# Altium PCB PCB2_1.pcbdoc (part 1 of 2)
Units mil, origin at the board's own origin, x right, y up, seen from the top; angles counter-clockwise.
Board outline 4577.16 x 3522.49 mil, 4 copper layers (Top Layer, Inner1, Inner2, Bottom Layer); 102 components, 86 nets, 382 pads, 182 vias.
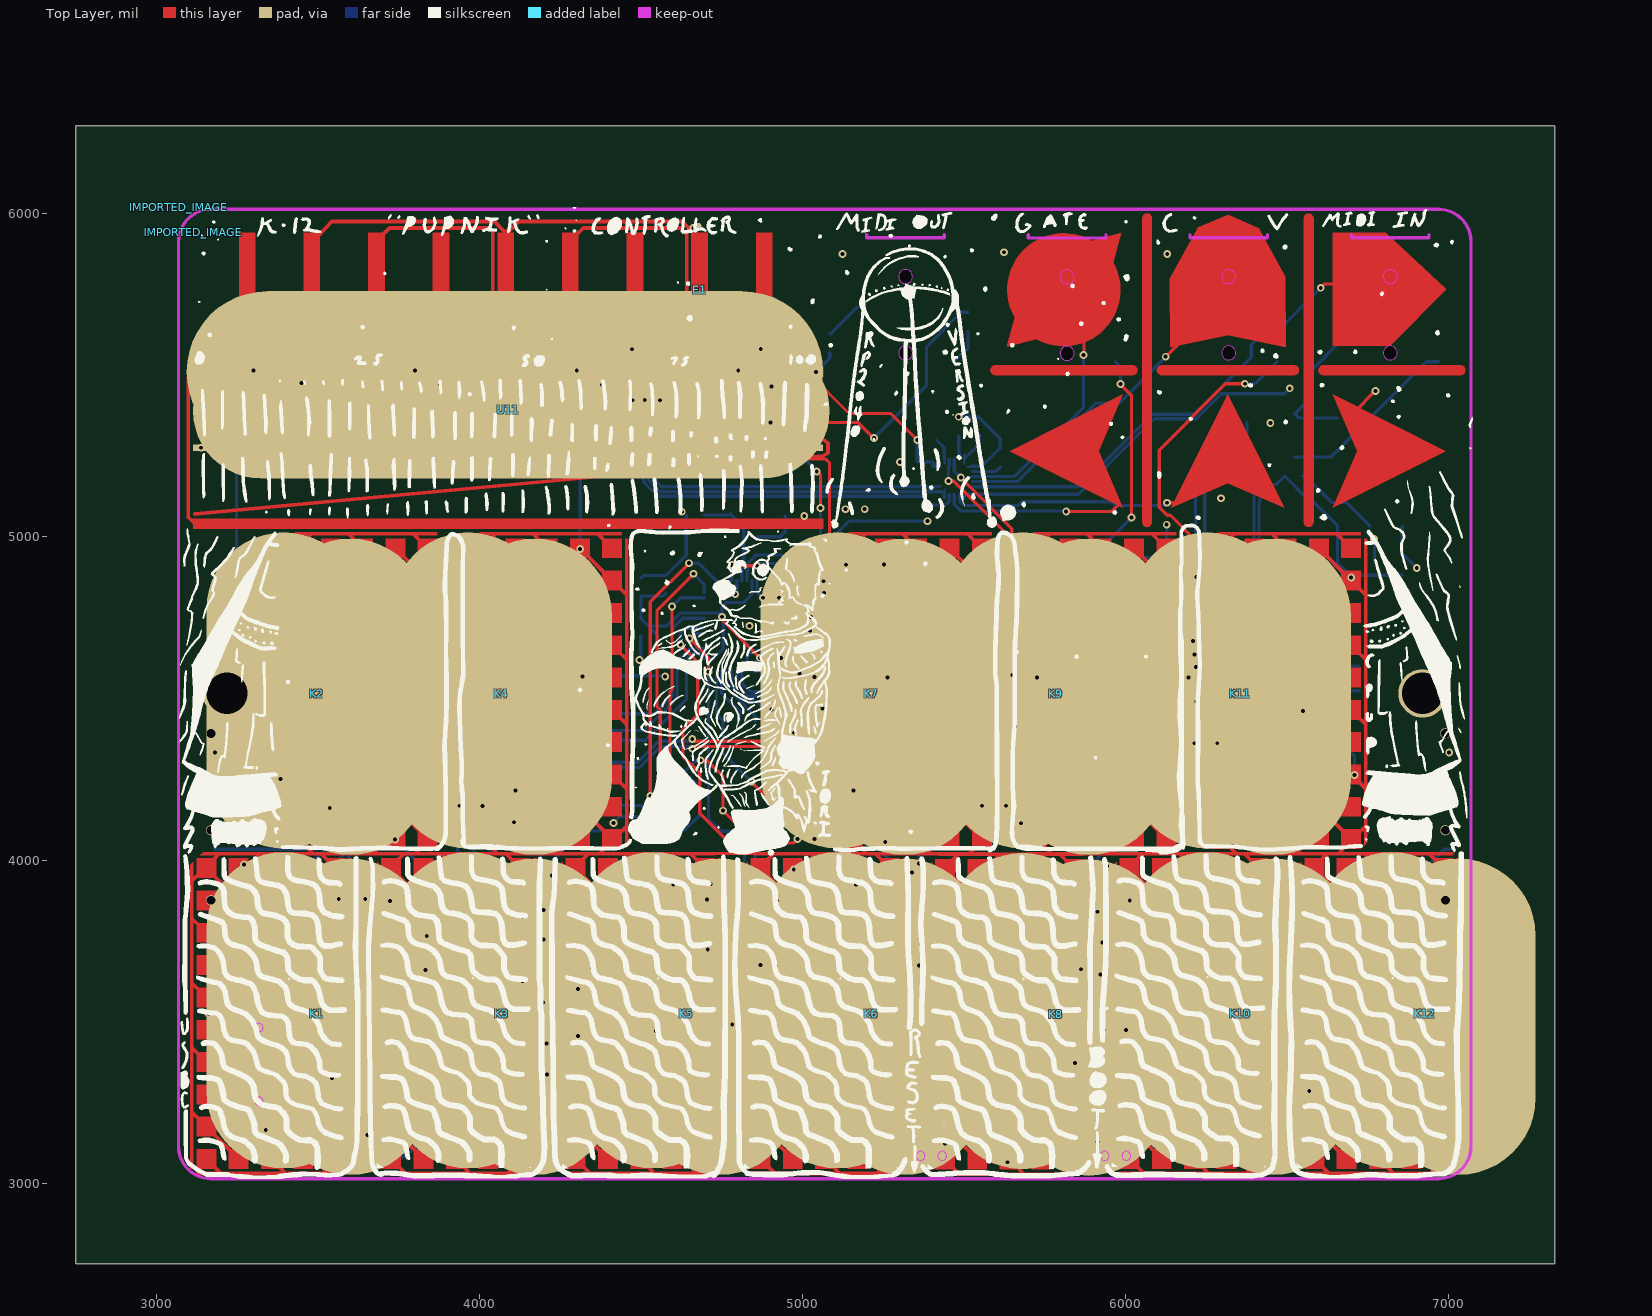
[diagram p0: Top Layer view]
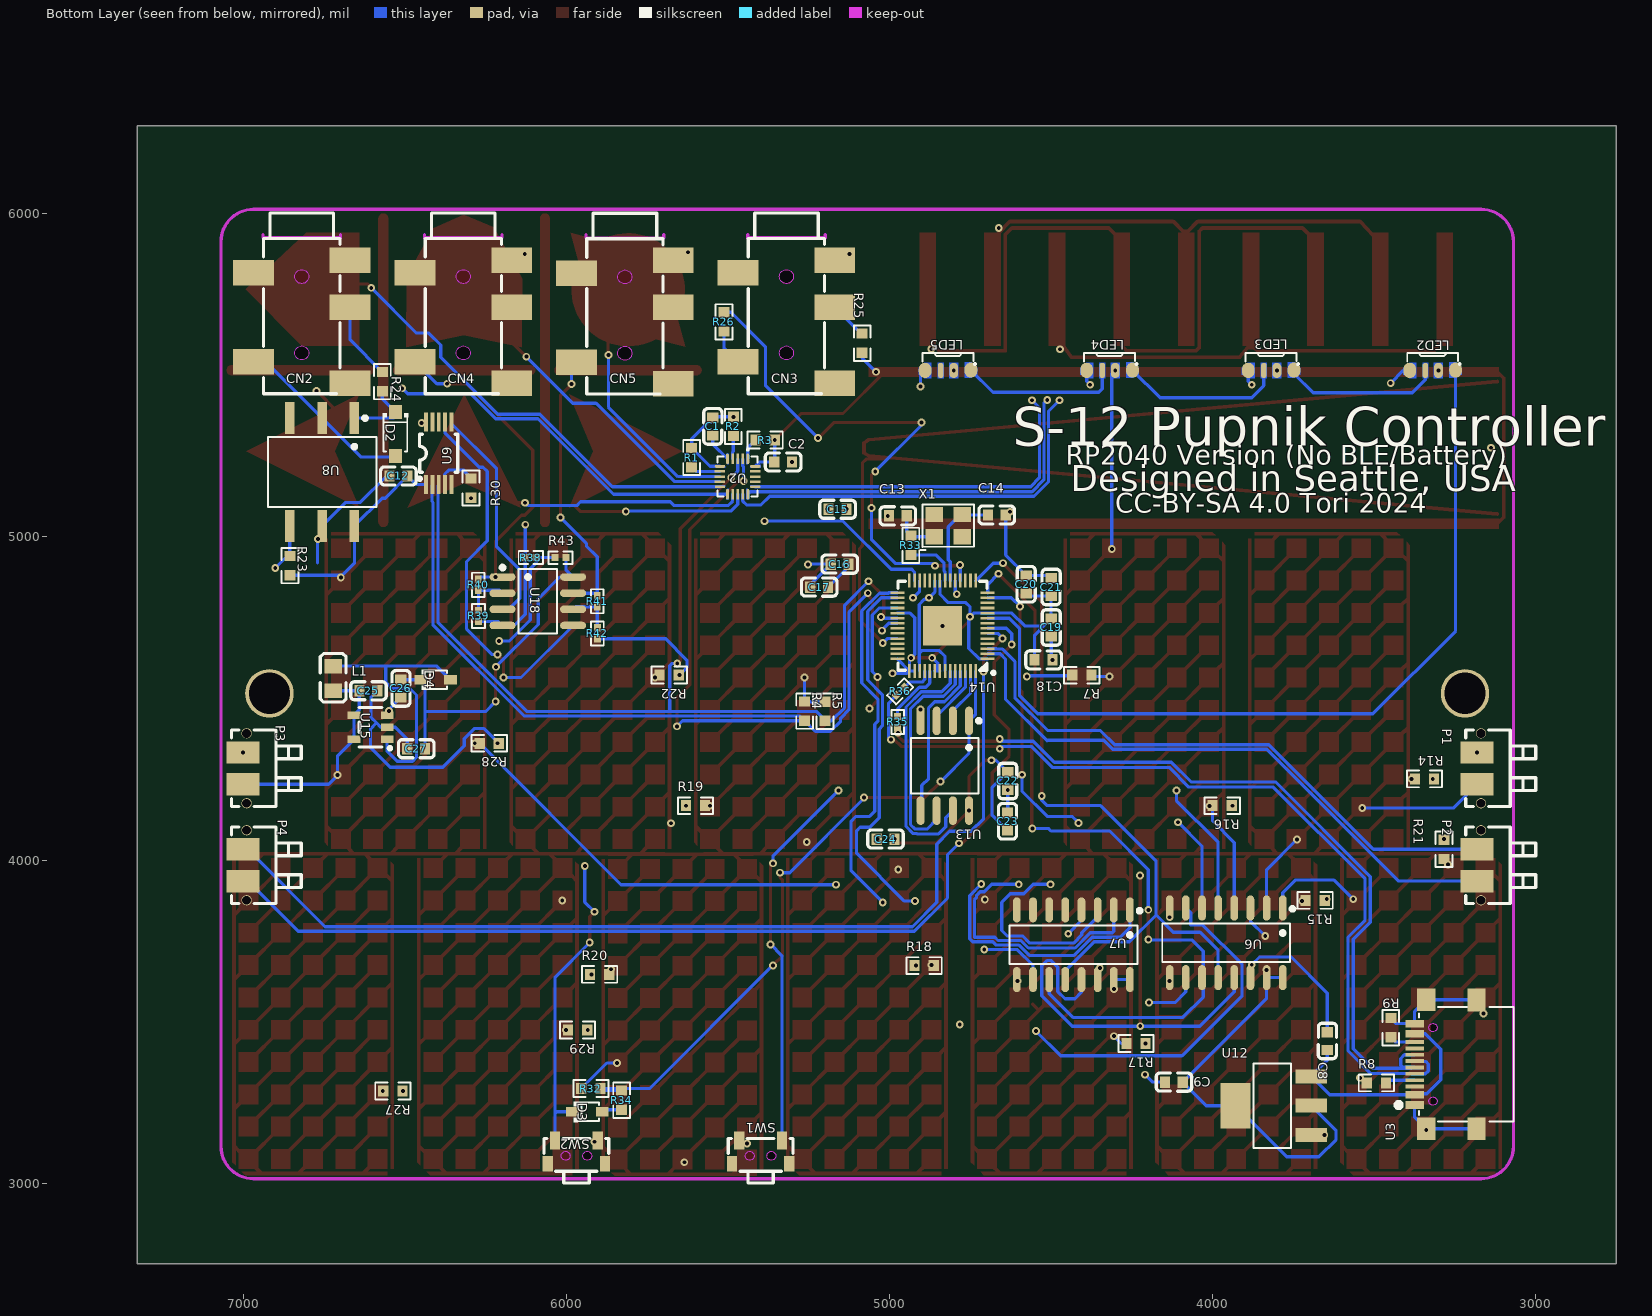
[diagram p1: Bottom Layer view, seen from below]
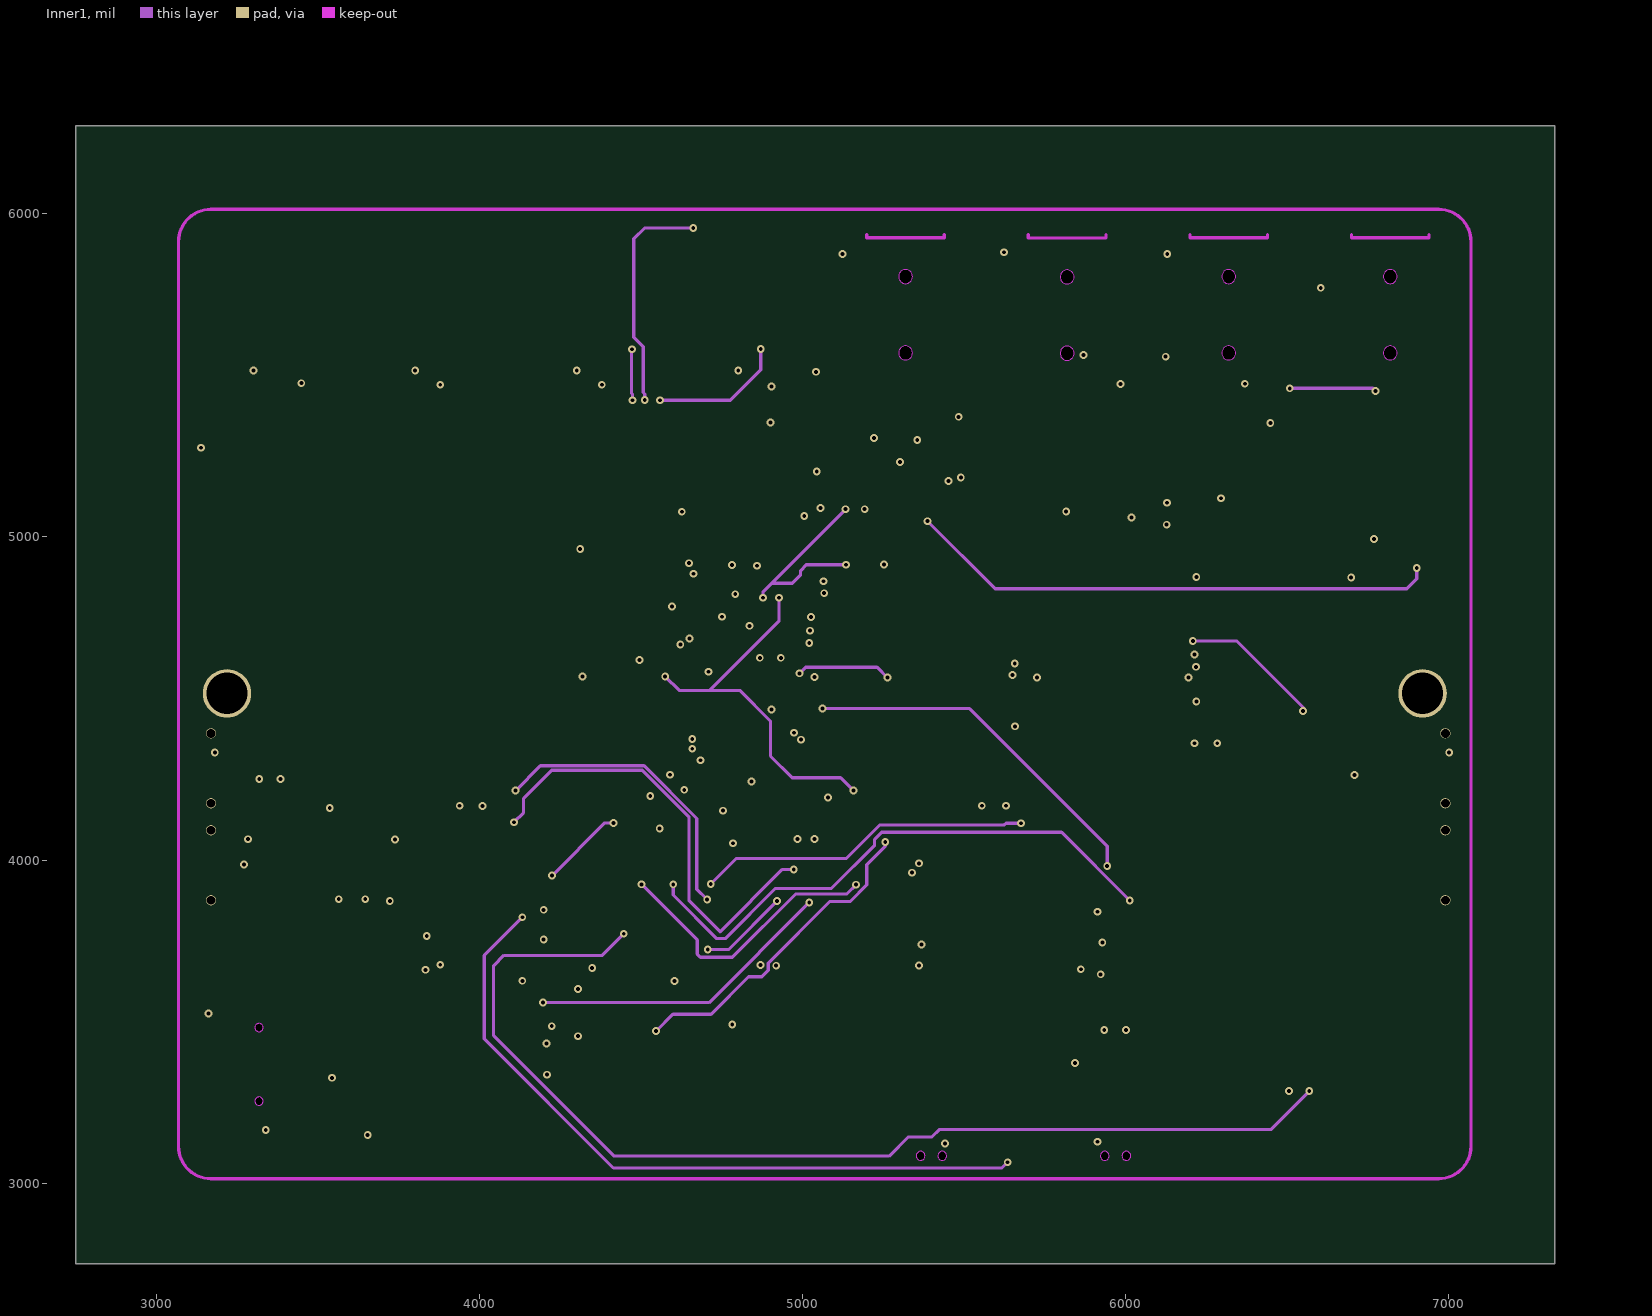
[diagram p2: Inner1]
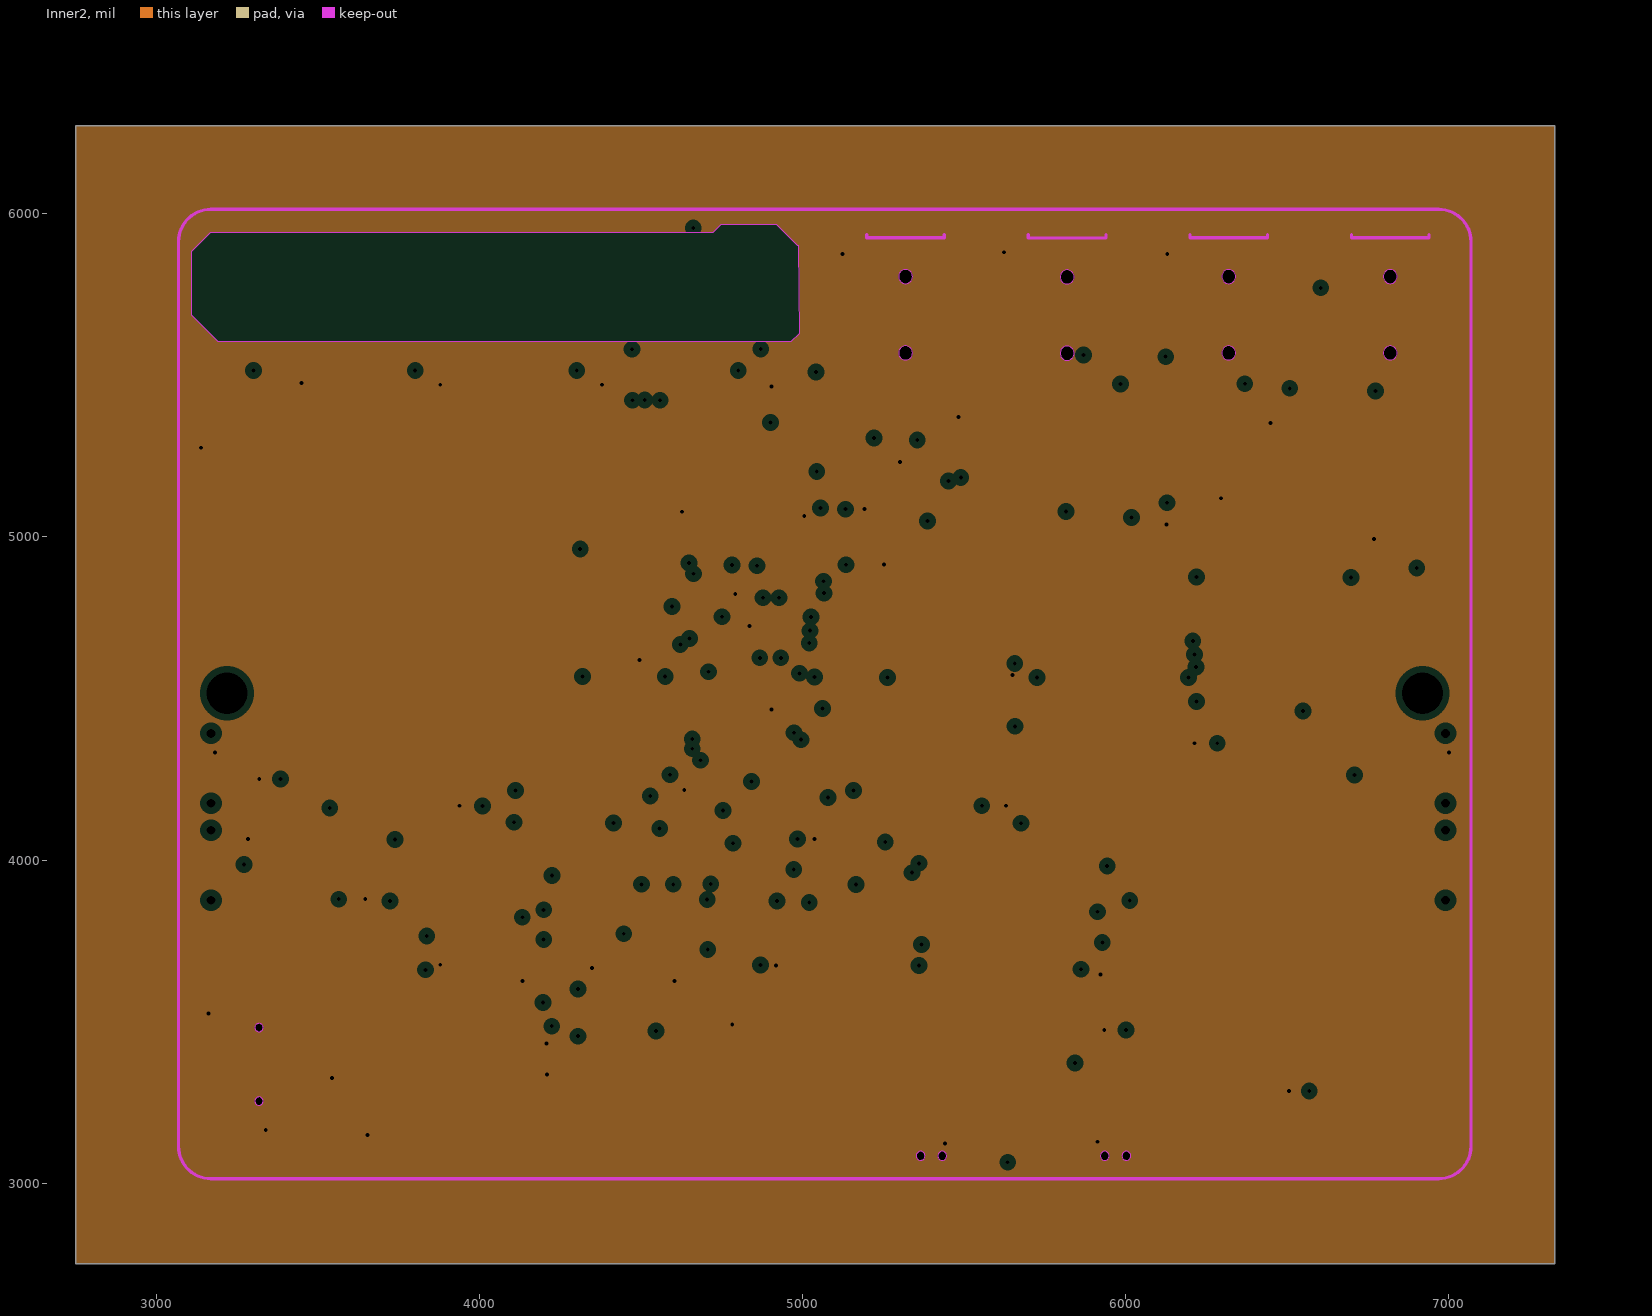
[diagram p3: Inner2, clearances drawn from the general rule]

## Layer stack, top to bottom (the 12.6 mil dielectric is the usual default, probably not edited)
Top Layer: signal copper (thickness not stored)
Dielectric: dielectric 12.6, FR-4, Dk 4.8
Inner1: signal copper (thickness not stored)
Dielectric: dielectric 12.6, FR-4, Dk 4.8
Inner2: plane copper (thickness not stored)
Dielectric: dielectric 12.6, FR-4, Dk 4.8
Bottom Layer: signal copper (thickness not stored)

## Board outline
7327.16,2750 2750,2750 2750,6272.49 7327.16,6272.49

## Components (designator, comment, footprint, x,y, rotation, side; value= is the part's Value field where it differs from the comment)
C1 "0.1u" C0603 5546.64,5341.97 r270 bottom
C2 "0.1u" C0603 5328.64,5231.97 r180 bottom
C8 "10u" C0603 3644.64,3439.85 r270 bottom
C9 "10u" C0603 4119.64,3312.97 r0 bottom
C12 "0.1u" C0603 6519.26,5188.72 r180 bottom
C13 "CAP_0603" C0603 4973.64,5064.97 r180 bottom
C14 "CAP_0603" C0603 4667.64,5067.97 r180 bottom
C15 "CAP_0603" C0603 5160.52,5085.97 r0 bottom
C16 "CAP_0603" C0603 5154.19,4916.04 r0 bottom
C17 "CAP_0603" C0603 5217.64,4844.97 r0 bottom
C18 "CAP_0603" C0603 4523.08,4619.53 r0 bottom
C19 "CAP_0603" C0603 4499.08,4720.09 r90 bottom
C20 "CAP_0603" C0603 4576.82,4853.09 r270 bottom
C21 "CAP_0603" C0603 4499.64,4844.97 r270 bottom
C22 "CAP_0603" C0603 4633.64,4244.97 r90 bottom
C23 "CAP_0603" C0603 4634.5,4119.65 r270 bottom
C24 "CAP_0603" C0603 5011.64,4064.97 r180 bottom
C25 "4.7u" C0603 6612.64,4523.97 r0 bottom
C26 "22p" C0603 6511.68,4531.07 r270 bottom
C27 "1u" C0603 6464.45,4344.69 r0 bottom
CN2 "MIDI IN" AUDIO-SMD_PJ-327A5JJ 6818.64,5665.97 r180 bottom
CN3 "MIDI OUT" AUDIO-SMD_PJ-327A5JJ 5318.64,5665.97 r180 bottom
CN4 "CV" AUDIO-SMD_PJ-327A5JJ 6318.64,5665.97 r180 bottom
CN5 "GT" AUDIO-SMD_PJ-327A5JJ 5818.64,5664.97 r180 bottom
D2 "1N4148W_C81598" SOD-123F_L2.7-W1.6-LS3.8-RD 6528.64,5318.97 r270 bottom
D3 "1N5819WS_C191023" SOD-323_L1.8-W1.3-LS2.5-RD 5934.64,3220.97 r180 bottom
D4 "1N5819WS_C191023" SOD-323_L1.8-W1.3-LS2.5-RD 6404.64,4557.97 r180 bottom
E1 "enc" enc 3236.85,5942.35 r0 top
IMPORTED_IMAGE "IMPORTED_IMAGE" IMPORTED_IMAGE 3070.08,6020.97 r0 top
IMPORTED_IMAGE "IMPORTED_IMAGE" IMPORTED_IMAGE 3113.64,5942.97 r0 top
K1 "key" key 3354.64,3524.97 r0 top
K2 "key" key 3639.64,4514.97 r180 top
K3 "key" key 3926.64,3524.97 r0 top
K4 "key" key 4210.64,4514.97 r180 top
K5 "key" key 4497.64,3524.97 r0 top
K6 "key" key 5069.64,3524.97 r0 top
K7 "key" key 5354.64,4514.97 r180 top
K8 "key" key 5640.64,3522.97 r0 top
K9 "key" key 5925.64,4514.97 r180 top
K10 "key" key 6211.64,3524.97 r0 top
K11 "key" key 6497.64,4514.97 r180 top
K12 "key" key 6783.64,3524.97 r0 top
L1 "CMI201209U2R2KT" L0805 6721.45,4562.39 r270 bottom
LED2 "SK6812SIDE-A-RVS" LED-SMD_4P-L4.0-W1.6-L 3318.64,5515.97 r0 bottom
LED3 "SK6812SIDE-A-RVS" LED-SMD_4P-L4.0-W1.6-L 3818.64,5515.97 r0 bottom
LED4 "SK6812SIDE-A-RVS" LED-SMD_4P-L4.0-W1.6-L 4318.64,5515.97 r0 bottom
LED5 "SK6812SIDE-A-RVS" LED-SMD_4P-L4.0-W1.6-L 4818.64,5515.97 r0 bottom
P1 "PogoPIN 2PIN 2.54mm" "POGOPIN 2PIN 2.5MM" 3078.64,4165.97 r270 bottom
P2 "PogoPIN 2PIN 2.54mm" "POGOPIN 2PIN 2.5MM" 3078.64,3865.97 r270 bottom
P3 "PogoPIN 2PIN 2.54mm" "POGOPIN 2PIN 2.5MM" 6898.64,4165.97 r270 bottom
P4 "PogoPIN 2PIN 2.54mm" "POGOPIN 2PIN 2.5MM" 6898.64,3865.97 r270 bottom
R1 "75k" R0603 5611.98,5245.63 r270 bottom
R2 "10k" R0603 5483.07,5342.12 r270 bottom
R3 "10k" R0603 5384.64,5299.97 r0 bottom
R4 "10k" R0603 5262.37,4460.89 r270 bottom
R5 "10k" R0603 5199.37,4460.6 r270 bottom
R7 "10k" R0603 4404.46,4572.11 r0 bottom
R8 "5.1k" R0603 3492.89,3310.64 r180 bottom
R9 "5.1k" R0603 3448.23,3481.26 r270 bottom
R14 "100K" R0603 3343.99,4251.29 r0 bottom
R15 "100K" R0603 3682.48,3875.29 r0 bottom
R16 "100K" R0603 3970.14,4168.29 r0 bottom
R17 "100K" R0603 4236.89,3432.29 r0 bottom
R18 "100K" R0603 4892.59,3673.29 r180 bottom
R19 "100K" R0603 5600.04,4168.29 r180 bottom
R20 "100K" R0603 5896.79,3646.29 r180 bottom
R21 "100K" R0603 3283.3,4033.31 r270 bottom
R22 "100K" R0603 5681.49,4572.46 r0 bottom
R23 "470" R0603 6855.3,4911.31 r270 bottom
R24 "220" R0603 6569.19,5480.67 r270 bottom
R25 "33" R0603 5084.16,5599.63 r270 bottom
R26 "10" R0603 5512.16,5665.59 r90 bottom
R27 "100K" R0603 6536.64,3284.97 r0 bottom
R28 "100K" R0603 6238.48,4361.46 r0 bottom
R29 "100K" R0603 5964.99,3474.46 r0 bottom
R30 "5.1k" R0603 6294.97,5151.26 r90 bottom
R32 "Res_0603" R0603 5923.64,3292.97 r180 bottom
R33 "Res_0603" R0603 4933.64,4973.97 r270 bottom
R34 "Res_0603" R0603 5828.64,3256.97 r270 bottom
R35 "Res_0402" R0402 4974.53,4427.42 r270 bottom
R36 "Res_0402" R0402 4966.64,4521.97 r315 bottom
R38 "Res_0402" R0402 6109.83,4936.4 r180 bottom
R39 "Res_0402" R0402 6271.52,4755.41 r90 bottom
R40 "Res_0402" R0402 6272.24,4852 r90 bottom
R41 "Res_0402" R0402 5904.24,4801 r270 bottom
R42 "Res_0402" R0402 5903.6,4701.72 r90 bottom
R43 "Res_0402" R0402 6018.24,4936 r180 bottom
SW1 "RST" SW-SMD_L4.7-W3.5-P3.35-EH 5398.64,3095.97 r0 bottom
SW2 "BOOT" SW-SMD_L4.7-W3.5-P3.35-EH 5968.64,3095.97 r0 bottom
U2 "MPR121QR2" QFN-20_L3.0-W3.0-P0.40-BL 5469.64,5186.97 r0 bottom
U3 "GT-USB-9047A" USB-C-SMD_GT-USB-9047A 3278.64,3367.97 r90 bottom
U6 "MCP3008-I/SL" SOIC-16_L9.9-W3.9-P1.27-LS6.0-BL 3957.64,3743.97 r0 bottom
U7 "MCP3008-I/SL" SOIC-16_L9.9-W3.9-P1.27-LS6.0-BL 4430.64,3737.97 r0 bottom
U8 "H11L1VSMT&amp;R" SMD-6_L8.6-W6.4-P2.54-LS9.4-BL 6755.64,5200.97 r0 bottom
U9 "MCP4728-E/UN" MSOP-10_L3.0-W3.0-P0.50-LS5.0-TL 6394.64,5258.97 r90 bottom
U11 "farts" farts 3093.64,5525.97 r0 top
U12 "AMS1117-3.3_C6186" SOT-223-3_L6.5-W3.4-P2.30-LS7.0-BR 3811.64,3239.97 r180 bottom
U13 "W25Q128JVSIQ" SOIC-8_L5.3-W5.3-P1.27-LS8.0-BL 4828.64,4291.97 r0 bottom
U14 "RP2040_C2040" LQFN-56_L7.0-W7.0-P0.4-EP 4835.64,4724.98 r0 bottom
U15 "TPS61041DBVR" SOT-23-5_L3.0-W1.7-P0.95-LS2.8-BR 6605.64,4410.97 r180 bottom
U18 "MCP6002T-I/SN" SOIC-8_L4.9-W3.9-P1.27-LS6.0-BL 6088.24,4801 r270 bottom
X1 "X322512MSB4SI" OSC-SMD_4P-L3.2-W2.5-BL 4817.64,5034.97 r180 bottom

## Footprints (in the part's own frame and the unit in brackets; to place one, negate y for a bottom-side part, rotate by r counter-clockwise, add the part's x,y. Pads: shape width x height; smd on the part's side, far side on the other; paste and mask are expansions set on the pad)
AUDIO-SMD_PJ-327A5JJ [mm]
  rect 3.2x2 smd: 1(3.8,4.85) 2(-3.8,3.85) 3(3.8,1.15) 4(-3.8,-3.15) 5(3.8,-4.85)
  Board Outline Layer lines w0.254: 3.048,6.604 -3.048,6.604 ; 3.048,6.604 -3.048,6.604 ; 3.048,6.604 3.048,6.858 3.048,6.604 ; -3.048,6.604 -3.048,6.858 -3.048,6.604
  Multi-Layer board cut-out: -0.55,3.55 -0.496,3.789 -0.343,3.98 -0.123,4.086 0.122,4.086 0.343,3.98 0.495,3.789 0.55,3.55 0.55,3.55 0.495,3.311 0.343,3.12 0.122,3.014 -0.123,3.014 -0.343,3.12 -0.496,3.311 -0.55,3.55
  Multi-Layer board cut-out: -0.55,-2.45 -0.496,-2.211 -0.343,-2.02 -0.123,-1.914 0.122,-1.914 0.343,-2.02 0.495,-2.211 0.55,-2.45 0.55,-2.45 0.495,-2.689 0.343,-2.88 0.122,-2.986 -0.123,-2.986 -0.343,-2.88 -0.496,-2.689 -0.55,-2.45
  Multi-Layer keep-out region: -0.55,3.55 -0.496,3.789 -0.343,3.98 -0.123,4.086 0.122,4.086 0.343,3.98 0.495,3.789 0.55,3.55 0.55,3.55 0.495,3.311 0.343,3.12 0.122,3.014 -0.123,3.014 -0.343,3.12 -0.496,3.311 -0.55,3.55
  Multi-Layer keep-out region: -0.55,-2.45 -0.496,-2.211 -0.343,-2.02 -0.123,-1.914 0.122,-1.914 0.343,-2.02 0.495,-2.211 0.55,-2.45 0.55,-2.45 0.495,-2.689 0.343,-2.88 0.122,-2.986 -0.123,-2.986 -0.343,-2.88 -0.496,-2.689 -0.55,-2.45
  silkscreen extent -3,-5.65 3,8.55
C0603 [mm]
  rect 0.8x0.9 smd: 1(-0.7,0) 2(0.7,0)
  silkscreen extent -1.41,-0.71 1.39,0.72
enc [mil]
  round 20 smd: 1(1645,-370) 2(1440,20) 3(1245,-375)
farts [mil]
  oval 1970x500 smd: 1(985,-15)
  oval 1970x420 smd: 2(1005,-135.69)
  rect 1950x20 smd: 3(995,-250)
  Top Layer region: 1970,-470 1970,-500 20,-500 20,-487.07 1.46,-468.54 1.46,-468.54 0.38,-466.91 0,-465 0,-465 0,-35 0.38,-33.09 1.46,-31.46 1.46,-31.46 1.46,-31.46 20,-12.93 20,0 1970,0 1970,-30 20,-30 20,-27.07 10,-37.07 10,-462.93 20,-472.93 20,-470
  Top Layer region: 25.46,-459.98 25.23,-459.99 25,-460 25,-460 23.09,-459.62 21.46,-458.54 20.38,-456.91 20,-455 20,-455 20.6,-452.63 22.24,-450.83 24.54,-450.02 24.54,-450.02 1968.42,-270.13 1980,-263.25 1980,-237.68 1968.28,-229.86 24.54,-49.98 24.54,-49.98 22.24,-49.17 20.6,-47.37 20,-45 20,-45 20.38,-43.09 21.46,-41.46 23.09,-40.38 25,-40 25,-40 25.23,-40.01 25.46,-40.02 25.46,-40.02 1970.46,-220.02 1970.46,-220.02 1971.67,-220.29 1972.77,-220.84 1972.77,-220.84 1972.77,-220.84 1987.77,-230.84 1987.77,-230.84 1989.41,-232.64 1990,-235 1990,-235 1990,-266.1 1989.34,-268.57 1987.55,-270.4 1987.55,-270.4 1987.55,-270.4 1972.55,-279.3 1971.54,-279.76 1970.46,-279.98 1970.46,-279.98 1970.46,-279.98
IMPORTED_IMAGE [mil]
  silkscreen extent 0,-3007 4004,0
key [mil]
  oval 480x980 smd: 1(40,10) 2(245,-10)
  Top Layer region: 191 vertices and 0 holes, not listed, extent -250,-480 230,500
  Top Layer region: 189 vertices and 0 holes, not listed, extent -230,-500 250,480
L0805 [mil]
  rect 44.59x54.21 smd: 1(-38.04,0) 2(38.04,0)
  silkscreen extent -77,-40 73,40
LED-SMD_4P-L4.0-W1.6-L [mm]
  oval 1x1.2 smd: 1(-1.8,-0.012) 4(1.8,0.013)
  oval 0.7x1.2 smd: 2(-0.45,0.013)
  oval 0.45x1.2 smd: 3(0.575,0.013)
  Top Layer region: 1.3,0.612 1.3,-0.588 1.85,-0.587 1.85,-0.188 2.3,-0.188 2.3,0.362 1.85,0.362 1.85,0.612
  Top Layer region: 0.35,-0.588 0.8,-0.588 0.8,0.612 0.35,0.612
  Top Layer region: -0.8,0.613 -0.8,-0.587 -0.1,-0.587 -0.1,0.613
  Top Layer region: -1.3,0.588 -1.3,-0.612 -1.85,-0.612 -1.85,-0.212 -2.3,-0.212 -2.3,0.338 -1.85,0.338 -1.85,0.588
  silkscreen extent -2.2,-1.36 2,-0.41
LQFN-56_L7.0-W7.0-P0.4-EP [mm]
  rect 1.1x0.2 smd: 1(-3.55,2.6) 2(-3.55,2.2) 3(-3.55,1.8) 4(-3.55,1.4) 5(-3.55,1) 6(-3.55,0.6) 7(-3.55,0.2) 8(-3.55,-0.2) 9(-3.55,-0.6) 10(-3.55,-1) 11(-3.55,-1.4) 12(-3.55,-1.8) 13(-3.55,-2.2) 14(-3.55,-2.6) 29(3.55,-2.6) 30(3.55,-2.2) 31(3.55,-1.8) 32(3.55,-1.4) 33(3.55,-1) 34(3.55,-0.6) 35(3.55,-0.2) 36(3.55,0.2) 37(3.55,0.6) 38(3.55,1) 39(3.55,1.4) 40(3.55,1.8) 41(3.55,2.2) 42(3.55,2.6)
  rect 0.2x1.1 smd: 15(-2.6,-3.55) 16(-2.2,-3.55) 17(-1.8,-3.55) 18(-1.4,-3.55) 19(-1,-3.55) 20(-0.6,-3.55) 21(-0.2,-3.55) 22(0.2,-3.55) 23(0.6,-3.55) 24(1,-3.55) 25(1.4,-3.55) 26(1.8,-3.55) 27(2.2,-3.55) 28(2.6,-3.55) 43(2.6,3.55) 44(2.2,3.55) 45(1.8,3.55) 46(1.4,3.55) 47(1,3.55) 48(0.6,3.55) 49(0.2,3.55) 50(-0.2,3.55) 51(-0.6,3.55) 52(-1,3.55) 53(-1.4,3.55) 54(-1.8,3.55) 55(-2.2,3.55) 56(-2.6,3.55)
  rect 3.1x3.1 smd: 57(0,0)
  silkscreen extent -4.13,-3.5 3.5,3.83
MSOP-10_L3.0-W3.0-P0.50-LS5.0-TL [mil]
  rect 59.05x12 smd: 1(-96.5,39.37) 2(-96.5,19.68) 3(-96.5,0) 4(-96.5,-19.69) 5(-96.5,-39.37) 6(96.5,-39.37) 7(96.5,-19.69) 8(96.5,0) 9(96.5,19.68) 10(96.5,39.37)
  silkscreen extent -84,-59 59,64
OSC-SMD_4P-L3.2-W2.5-BL [mm]
  rect 1.4x1.2 smd: 1(-1.1,-0.875) 2(1.1,-0.875) 3(1.1,0.875) 4(-1.1,0.875)
  silkscreen extent -2.29,-1.9 2.03,1.65
"POGOPIN 2PIN 2.5MM" [mm]
  rect 1.75x2.6 smd: 1(-4.25,-2.6) 2(-1.75,-2.6)
  round 0.8 hole 0.7: 3(-5.75,-2.3) 4(-0.25,-2.3)
  silkscreen extent -6,-3.5 0,2
QFN-20_L3.0-W3.0-P0.40-BL [mm]
  oval 0.224x0.825 smd: 1(-0.8,-1.388) 5(0.8,-1.388) 11(0.8,1.388) 15(-0.8,1.388)
  rect 0.2x0.825 smd: 2(-0.4,-1.388) 3(0,-1.388) 4(0.4,-1.388) 12(0.4,1.388) 13(0,1.388) 14(-0.4,1.388)
  oval 0.825x0.224 smd: 6(1.388,-0.8) 10(1.388,0.8) 16(-1.387,0.8) 20(-1.388,-0.8)
  rect 0.825x0.2 smd: 7(1.388,-0.4) 8(1.388,0) 9(1.388,0.4) 17(-1.387,0.4) 18(-1.387,0) 19(-1.387,-0.4)
  Top Layer region: 0.688,-1.8 0.688,-0.975 0.8,-0.975 0.912,-1.388 0.912,-1.8
  Top Layer region: -1.8,-0.688 -0.975,-0.688 -0.975,-0.8 -1.388,-0.912 -1.8,-0.912
  Top Layer region: -0.688,1.8 -0.688,0.975 -0.8,0.975 -0.912,1.388 -0.912,1.8
  Top Layer region: 1.8,0.688 0.975,0.688 0.975,0.8 1.388,0.912 1.8,0.912
  Top Layer region: 1.8,-0.688 0.975,-0.688 0.975,-0.8 1.388,-0.912 1.8,-0.912
  Top Layer region: 0.688,1.8 0.688,0.975 0.8,0.975 0.912,1.388 0.912,1.8
  Top Layer region: -1.8,0.688 -0.975,0.688 -0.975,0.8 -1.387,0.912 -1.8,0.912
  Top Layer region: -0.688,-1.8 -0.688,-0.975 -0.8,-0.975 -0.912,-1.388 -0.912,-1.8
  silkscreen extent -1.58,-2.17 1.58,1.58
R0402 [mm]
  rect 0.566x0.54 smd: 1(-0.433,0) 2(0.433,0)
  silkscreen extent -0.94,-0.5 0.94,0.5
R0603 [mil]
  rect 31.75x34.02 smd: 1(-29.66,0) 2(29.66,0)
  silkscreen extent -55,-26 55,26
SMD-6_L8.6-W6.4-P2.54-LS9.4-BL [mil]
  rect 29.76x99.37 smd: 1(-100,-166.81) 2(0,-166.81) 3(100,-166.81) 4(100,166.81) 5(0,166.81) 6(-100,166.81)
  silkscreen extent -168,-173 168,108
SOD-123F_L2.7-W1.6-LS3.8-RD [mm]
  rect 1.1x1 smd: 1(-1.735,0) 2(1.735,0)
  silkscreen extent -1.6,-1 1.38,1
SOD-323_L1.8-W1.3-LS2.5-RD [mm]
  rect 1x0.75 smd: 1(-1.173,0) 2(1.173,0)
  silkscreen extent -1.08,-0.8 0.9,0.8
SOIC-8_L4.9-W3.9-P1.27-LS6.0-BL [mm]
  oval 0.588x2.045 smd: 1(-1.905,-2.772) 2(-0.635,-2.772) 3(0.635,-2.772) 4(1.905,-2.772) 5(1.905,2.772) 6(0.635,2.772) 7(-0.635,2.772) 8(-1.905,2.772)
  silkscreen extent -2.8,-2.92 2.53,1.52
SOIC-8_L5.3-W5.3-P1.27-LS8.0-BL [mm]
  oval 0.63x2.25 smd: 1(-1.905,-3.53) 2(-0.635,-3.53) 3(0.635,-3.53) 4(1.905,-3.53) 5(1.905,3.53) 6(0.635,3.53) 7(-0.635,3.53) 8(-1.905,3.53)
  silkscreen extent -2.82,-3.68 2.64,2.18
SOIC-16_L9.9-W3.9-P1.27-LS6.0-BL [mil]
  oval 23.7x77.6 smd: 1(-175,-107.7) 2(-125,-107.7) 3(-75,-107.7) 4(-25,-107.7) 5(25,-107.7) 6(75,-107.7) 7(125,-107.7) 8(175,-107.7) 9(175,107.7) 10(125,107.7) 11(75,107.7) 12(25,107.7) 13(-25,107.7) 14(-75,107.7) 15(-125,107.7) 16(-175,107.7)
  silkscreen extent -211,-111 198,60
SOT-23-5_L3.0-W1.7-P0.95-LS2.8-BR [mm]
  rect 1x0.6 smd: 1(1.3,-0.95) 2(1.3,0) 3(1.3,0.95) 4(-1.3,0.95) 5(-1.3,-0.95)
  silkscreen extent -0.9,-1.78 1.65,1.55
SOT-223-3_L6.5-W3.4-P2.30-LS7.0-BR [mm]
  rect 2.5x1.1 smd: 1(2.97,-2.3) 2(2.97,0) 3(2.97,2.3)
  rect 2.34x3.6 smd: 4(-2.97,0)
  silkscreen extent -1.57,-3.33 1.37,3.33
SW-SMD_L4.7-W3.5-P3.35-EH [mm]
  rect 0.8x1.4 smd: 1(-1.675,-0.917) 2(1.675,-0.917)
  rect 0.8x1.2 smd: 3(-2.25,0.917) 4(2.25,0.917)
  Multi-Layer board cut-out: -0.5,0.282 -0.535,0.131 -0.632,0.009 -0.772,-0.059 -0.928,-0.059 -1.068,0.009 -1.165,0.131 -1.2,0.282 -1.2,0.282 -1.165,0.434 -1.068,0.556 -0.928,0.624 -0.772,0.624 -0.632,0.556 -0.535,0.434 -0.5,0.282
  Multi-Layer board cut-out: 1.2,0.282 1.165,0.131 1.068,0.009 0.928,-0.059 0.772,-0.059 0.632,0.009 0.535,0.131 0.5,0.282 0.5,0.282 0.535,0.434 0.632,0.556 0.772,0.624 0.928,0.624 1.068,0.556 1.165,0.434 1.2,0.282
  Multi-Layer keep-out region: -0.5,0.282 -0.535,0.131 -0.632,0.009 -0.772,-0.059 -0.928,-0.059 -1.068,0.009 -1.165,0.131 -1.2,0.282 -1.2,0.282 -1.165,0.434 -1.068,0.556 -0.928,0.624 -0.772,0.624 -0.632,0.556 -0.535,0.434 -0.5,0.282
  Multi-Layer keep-out region: 1.2,0.282 1.165,0.131 1.068,0.009 0.928,-0.059 0.772,-0.059 0.632,0.009 0.535,0.131 0.5,0.282 0.5,0.282 0.535,0.434 0.632,0.556 0.772,0.624 0.928,0.624 1.068,0.556 1.165,0.434 1.2,0.282
  silkscreen extent -2.54,-1.07 2.54,2.43
USB-C-SMD_GT-USB-9047A [mm]
  rect 1.8x1.45 smd: 12(-5.07,1.524) 13(5.07,1.524)
  rect 1.8x1.4 smd: 14(-5.07,-2.436) 15(5.07,-2.436)
  rect 0.6x1.45 smd: A1B12(-3.2,2.437) A4B9(-2.4,2.437) A9B4(2.4,2.437) A12B1(3.2,2.437)
  rect 0.3x1.45 smd: A5(-1.25,2.437) A6(-0.25,2.437) A7(0.25,2.437) A8(1.25,2.437) B5(1.75,2.437) B6(0.75,2.437) B7(-0.75,2.437) B8(-1.75,2.437)
  Multi-Layer board cut-out: 2.89,1.319 3.031,1.286 3.144,1.196 3.207,1.066 3.207,0.921 3.144,0.791 3.031,0.701 2.89,0.669 2.89,0.669 2.749,0.701 2.636,0.791 2.573,0.921 2.573,1.066 2.636,1.196 2.749,1.286 2.89,1.319
  Multi-Layer board cut-out: -2.89,1.318 -2.749,1.286 -2.636,1.196 -2.573,1.065 -2.573,0.921 -2.636,0.791 -2.749,0.7 -2.89,0.668 -2.89,0.668 -3.031,0.7 -3.144,0.791 -3.207,0.921 -3.207,1.065 -3.144,1.196 -3.031,1.286 -2.89,1.318
  Multi-Layer keep-out region: 2.89,1.319 3.031,1.286 3.144,1.196 3.207,1.066 3.207,0.921 3.144,0.791 3.031,0.701 2.89,0.669 2.89,0.669 2.749,0.701 2.636,0.791 2.573,0.921 2.573,1.066 2.636,1.196 2.749,1.286 2.89,1.319
  Multi-Layer keep-out region: -2.89,1.318 -2.749,1.286 -2.636,1.196 -2.573,1.065 -2.573,0.921 -2.636,0.791 -2.749,0.7 -2.89,0.668 -2.89,0.668 -3.031,0.7 -3.144,0.791 -3.207,0.921 -3.207,1.065 -3.144,1.196 -3.031,1.286 -2.89,1.318
  silkscreen extent -4.5,-5.36 4.5,3.89

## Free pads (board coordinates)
  round 150 hole 128: 73(3218.64,4515.97) 73(6918.64,4515.97)

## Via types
v1: diameter 24.02, hole 12.01, Top Layer to Bottom Layer, 182 vias

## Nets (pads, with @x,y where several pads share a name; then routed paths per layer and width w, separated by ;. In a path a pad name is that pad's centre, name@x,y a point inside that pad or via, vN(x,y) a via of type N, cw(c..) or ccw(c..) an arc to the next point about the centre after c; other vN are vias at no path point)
1V2: C15.1 C16.1 C17.1 U14.23 U14.45 U14.50 | length 1209.6
  Inner1 w10: v1(4877.64,4811.97) 4877.64,4830.65 4903.96,4856.97 ; v1(5132.96,5085.97) 4903.96,4856.97 ; v1(5134.64,4913.97) 5011.64,4913.97 4993.64,4895.97 4993.64,4882.97 4967.64,4856.97 4903.96,4856.97
  Bottom Layer w10: U14.50@4827.76,4585.21 4827.76,4630.09 4846.64,4648.97 4898.64,4648.97 4906.5,4641.11 4906.5,4611.11 ; U14.23@4859.26,4864.74 4859.26,4829.35 4881.64,4806.97 4891.64,4806.97 4907.64,4790.97 4907.64,4612.25 4906.5,4611.11 ; U14.45@4906.5,4585.21 4906.5,4611.11 ; C16.1@5126.64,4916.04 5126.64,4908.41 C17.1@5190.08,4844.97
3V3: C2.1 C9.1 C12.2 C18.2 C19.2 C20.2 C21.2 C22.2 C23.2 C24.2 C25.2 K1.1 K2.1 K3.1 K4.1 K5.1 K6.1 K7.1 K8.1 K9.1 K10.1 K11.1 K12.1 L1.2 LED2.2 LED3.2 LED4.2 LED5.2 P1.2 P3.2 R3.1 R4.1 R5.1 R7.1 R23.2 R25.2 R32.1 U2.20 U6.15 U6.16 U7.15 U7.16 U8.6 U9.1 U11.1 U12.2 U12.4 U13.8 U14.1 U14.10 U14.22 U14.33 U14.42 U14.43 U14.44 U14.48 U14.49 U15.4 U15.5 | length 8224.7
  Top Layer w10: U11.1@4078.64,5510.97 5014.64,5510.97 5143.64,5381.97 5272.98,5381.97 v1(5354.98,5299.97) ; K5.1@4537.64,3534.97 K5.1@4556.66,3553.98 ; v1(4683.64,4308.97) 4703.64,4308.97 4753.64,4258.97 v1(4753.64,4152.99) 4853.64,4052.99 ; 4728.64,4019.97 4853.64,4019.97 ; v1(4750.64,4752.97) 4750.64,4742.97 v1(4867.64,4625.97) v1(4932.64,4625.97) ; 4855.64,4021.97 4853.64,4019.97 ; v1(4984.08,4064.97) 4972.1,4052.99 4853.64,4052.99 ; 4853.64,4019.97 4853.64,4052.99
  Inner1 w10: v1(4990.64,4577.97) 5009.64,4596.97 5230.5,4596.97 v1(5262.37,4565.1)
  Bottom Layer w10: P1.2@3181,4234.87 3254.9,4160.97 v1(3536.64,4160.97) ; U12.2@3694.71,3239.97 3617.64,3162.89 3617.64,3134.97 3670.64,3081.97 3770.57,3081.97 U12.4@3928.57,3239.97 4019.08,3239.97 C9.1@4092.08,3312.97 3832.64,3572.41 U6.15@3832.64,3636.27 U6.16@3782.64,3636.27 ; U7.16@4255.64,3630.27 U7.15@4305.64,3630.27 ; v1(4300.93,5515.47) 4311.64,5504.76 v1(4311.64,4962.97) ; v1(4318.64,4567.97) 4370.66,4567.97 R7.1@4374.8,4572.11 ; C18.2@4550.64,4619.53 4550.64,4696.09 4521.97,4724.76 ; C20.2@4576.82,4825.53 4568.7,4817.41 C21.2@4499.64,4817.41 4499.64,4748.21 C19.2@4499.08,4747.65 4521.97,4724.76 ; C23.2@4634.5,4092.09 4682.64,4140.23 4682.64,4223.53 C22.2@4633.64,4272.53 4670.08,4308.97 v1(4683.64,4308.97) ; U14.1@4695.87,4622.61 4722.52,4622.61 4754.64,4654.73 4754.64,4748.97 v1(4750.64,4752.97) ; U14.22@4843.51,4864.74 4843.51,4822.84 4817.67,4797 4763.67,4797 4750.64,4783.97 v1(4750.64,4752.97) ; U14.48@4860.09,4586.04 U14.48@4859.26,4585.21 U14.49@4843.51,4585.21 4850.63,4592.33 4850.63,4608.96 v1(4867.64,4625.97) ; U14.44@4922.25,4585.21 U14.43@4938,4585.21 ; U14.42@4975.41,4622.61 U14.43@4938,4585.21 ; U14.33@4975.41,4764.34 4936.02,4764.34 4921.66,4749.98 4921.66,4636.95 v1(4932.64,4625.97) 4938.01,4620.6 U14.43@4938,4585.21 ; v1(4990.64,4577.97) 4945.25,4577.97 U14.43@4938,4585.21 ; v1(5041.64,5510.97) 5084.16,5553.49 R25.2@5084.16,5569.97 ; R5.1@5199.37,4490.26 5262.07,4490.26 R4.1@5262.37,4490.55 v1(5262.37,4565.1) ; v1(5354.98,5299.97) 5354.98,5233.19 C2.1@5356.2,5231.97 5401.51,5231.97 U2.20@5415.01,5218.47 ; v1(5842.64,3371.97) 5874.3,3371.97 R32.1@5953.3,3292.97 ; U9.1@6434.01,5162.47 6465.45,5162.47 C12.2@6491.7,5188.72 6560.45,5119.97 6569.83,5119.97 U8.6@6655.64,5034.16 6655.64,4918.97 6692.96,4881.65 R23.2@6855.3,4881.65 ; C25.2@6640.2,4523.97 C25.2@6640.59,4524.35 ; L1.2@6721.45,4524.35 C25.2@6640.59,4524.35 ; P3.2@7001,4234.87 6735.74,4234.87 v1(6707.64,4262.97) 6707.64,4322.75 U15.5@6656.83,4373.57 U15.4@6656.83,4448.37 6640.59,4464.61 C25.2@6640.59,4524.35 ; 4521.97,4724.76 4581.43,4724.76 4621.02,4764.34 U14.10@4695.87,4764.34 4739.27,4764.34 v1(4750.64,4752.97)
  other v1: 4304.64,3600.97 3832.64,3660.31 6697.64,4874.69 3300.93,5515.47 3800.93,5515.47 4800.93,5515.47
$1N143: R1.2 U2.7 | length 93.2
  Bottom Layer w10: U2.7@5524.28,5202.72 5598.73,5202.72 R1.2@5611.98,5215.97
$1N157: R2.2 U2.4 | length 71.8
  Bottom Layer w10: R2.2@5483.07,5312.46 5483.07,5265.16 5485.4,5262.84 U2.4@5485.4,5241.6
$1N175: R3.2 U2.1 | length 68.2
  Bottom Layer w10: R3.2@5414.3,5299.97 5438.15,5276.12 U2.1@5438.15,5241.6
$1N193: C1.2 U2.5 | length 91.7
  Bottom Layer w10: U2.5@5501.15,5241.6 5546.64,5287.09 C1.2@5546.64,5314.41
$1N1108: LED2.3 LED3.1 | length 487.9
  Bottom Layer w10: LED2.3@3341.28,5515.47 3341.28,5486.85 3382.16,5445.97 3688.64,5445.97 3747.78,5505.11 LED3.1@3747.78,5516.46
$1N1109: LED3.3 LED4.1 | length 504.5
  Bottom Layer w10: LED3.3@3841.28,5515.47 3841.28,5468.33 3878.64,5430.97 4162.29,5430.97 LED4.1@4247.78,5516.46
$1N1133: LED4.3 LED5.1 | length 496.3
  Bottom Layer w10: LED4.3@4341.28,5515.47 4341.28,5458.33 4351.65,5447.96 4679.28,5447.96 LED5.1@4747.78,5516.46
$1N1275: CN2.4 D2.2 U8.2 | length 567.8
  Bottom Layer w10: D2.2@6522.64,5247.04 6634.9,5247.04 U8.2@6755.64,5367.78 6929.81,5541.95 CN2.4@6968.24,5541.95
$1N1289: CN2.3 R24.1 | length 242.3
  Bottom Layer w10: R24.1@6569.19,5510.33 6669.04,5610.19 CN2.3@6669.04,5711.24
$1N1636: R8.2 U3.A5 | length 92
  Bottom Layer w10: U3.A5@3374.57,3318.76 3455.11,3318.76 R8.2@3463.23,3310.64
$1N1637: R9.2 U3.B5 | length 79.8
  Bottom Layer w10: U3.B5@3374.57,3436.87 3433.5,3436.87 R9.2@3448.23,3451.59
$1N1720: D2.1 R24.2 U8.1 | length 227.8
  Bottom Layer w10: R24.2@6569.19,5451.01 6569.19,5427.44 6522.64,5380.9 6535.76,5367.78 U8.1@6655.64,5367.78
$1N1727: CN3.4 R26.1 | length 112.2
  Bottom Layer w10: CN3.4@5468.24,5541.95 5512.16,5585.87 R26.1@5512.16,5635.93
$1N1728: CN3.3 R25.1 | length 118.8
  Bottom Layer w10: R25.1@5084.16,5629.29 5087.1,5629.29 CN3.3@5169.04,5711.24
$1N1745: R30.2 U9.4 | length 131.6
  Bottom Layer w10: R30.2@6292.97,5180.92 6317.01,5204.97 ; 6317.01,5206.97 6363.64,5206.97 6376.95,5193.66 U9.4@6376.95,5161.47
$1N13713: U13.6 U14.52 | length 695.7
  Bottom Layer w10: U14.52@4796.27,4585.21 4796.27,4543.34 4832.64,4506.97 4895.64,4506.97 4934.64,4467.97 4934.64,4109.97 4920.64,4095.97 4883.64,4095.97 4853.64,4125.97 U13.6@4853.64,4152.99
$1N13723: U13.5 U14.53 | length 500.9
  Bottom Layer w10: U14.53@4780.52,4585.21 4780.52,4538.85 4829.4,4489.97 4859.64,4489.97 4878.64,4470.97 4878.64,4251.97 4899.64,4230.97 4899.64,4156.99 U13.5@4903.64,4152.99
$1N13771: U13.2 U14.55 | length 176.9
  Bottom Layer w10: U14.55@4749.02,4585.21 4749.02,4516.59 4803.64,4461.97 U13.2@4803.64,4430.95
$1N13787: U13.3 U14.54 | length 191.1
  Bottom Layer w10: U14.54@4764.77,4585.21 4764.77,4534.8 4853.64,4445.93 U13.3@4853.64,4430.95
$1N13805: U13.7 U14.51 | length 775.4
  Bottom Layer w10: U13.7@4803.64,4152.99 4825.64,4130.99 4825.64,4102.97 4847.64,4080.97 4913.64,4080.97 4914.63,4081.95 4926.45,4081.95 4948.66,4104.16 4948.66,4473.77 4901.45,4520.98 4838.45,4520.98 4812.02,4547.41 U14.51@4812.02,4585.21
$1N14059: R33.2 U14.21 | length 168.9
  Bottom Layer w10: U14.21@4827.76,4864.74 4827.76,4891.4 4830.64,4894.28 4830.64,4918.97 4855.98,4944.31 R33.2@4933.64,4944.31
$1N14171: C13.2 R33.1 X1.1 | length 140.5
  Bottom Layer w10: X1.1@4860.95,5000.52 4930.53,5000.52 R33.1@4933.64,5003.63 4946.08,5016.07 C13.2@4946.08,5064.97
$1N14175: C14.1 U14.20 X1.3 | length 306.7
  Bottom Layer w10: C14.1@4695.2,5067.97 4772.88,5067.97 X1.3@4774.33,5069.42 ; X1.3@4776.33,5072.28 4817.64,5030.97 4817.64,4928.97 4812.02,4923.35 U14.20@4812.02,4864.74
$1N14526: D3.2 R34.2 | length 62.5
  Bottom Layer w10: R34.2@5828.64,3227.31 5882.14,3227.31 D3.2@5888.48,3220.97
$1N14739: U11.2 U14.38 | length 716.4
  Top Layer w10: U11.2@5013.64,5240.97 5071.64,5240.97 5083.64,5228.97 5083.64,4972.97 5092.64,4963.97 5092.64,4743.97 v1(5020.64,4671.97)
  Bottom Layer w10: U14.38@4975.41,4685.6 5007.01,4685.6 v1(5020.64,4671.97)
$1N16821: E1.1 U2.16 | length 1556.4
  Inner1 w10: v1(4558.64,5422.97) 4776.64,5422.97 4870.64,5516.97 v1(4870.64,5581.97)
  Bottom Layer w10: v1(4558.64,5422.97) 4535.67,5400 4535.67,5182.58 4562.78,5155.47 U2.16@5415.02,5155.47
$1N16823: E1.2 U2.15 | length 1897
  Inner1 w10: v1(4511.64,5423.97) 4511.64,5441.97 4506.64,5446.97 4506.64,5588.97 4477.64,5617.97 4477.64,5922.97 4510.64,5955.97 v1(4661.64,5955.97)
  Bottom Layer w10: v1(4511.64,5423.97) 4521.66,5413.95 4521.66,5176.77 4558.37,5140.06 5430.43,5140.06 U2.15@5438.15,5132.34
$1N16825: E1.3 U2.14 | length 1428.1
  Inner1 w10: v1(4471.64,5580.97) 4470.64,5579.97 4470.64,5444.97 4473.64,5441.97 v1(4473.64,5422.97)
  Bottom Layer w10: v1(4473.64,5422.97) 4507.64,5388.97 4507.64,5170.97 4552.55,5126.06 5370.64,5126.06 5397.73,5098.97 5441.77,5098.97 5453.9,5111.1 U2.14@5453.9,5132.34
$1N18627: R36.1 U14.46 | length 100.6
  Bottom Layer w10: U14.46@4890.76,4585.21 4890.64,4585.09 4890.64,4558.97 4898.64,4550.97 4937.64,4550.97 R36.1@4954.59,4534.02
$1N18632: R35.1 U14.47 | length 193.5
  Bottom Layer w10: U14.47@4875.01,4585.21 4875.01,4547.63 4887.64,4535 4907.25,4535 4974.53,4467.72 R35.1@4974.53,4444.46
$1N23602: D4.2 L1.1 U15.1 | length 880.6
  Bottom Layer w10: D4.2@6358.48,4557.97 6400.94,4600.43 6558.75,4600.43 ; U15.1@6554.46,4373.57 6554.46,4336.78 6523.64,4305.97 6475.64,4305.97 6463.64,4317.97 6463.64,4510.97 6483.64,4530.97 6539.64,4530.97 6558.75,4550.07 6558.75,4600.43 ; L1.1@6721.45,4600.43 6558.75,4600.43
$1N23921: C26.2 R38.2 R43.1 U15.3 | length 884.9
  Inner1 w10: v1(6207.64,4677.97) 6343.64,4677.97 v1@6551.64,4469.97
  Bottom Layer w10: R43.1@6035.28,4936 6035.68,4936.4 R38.2@6092.79,4936.4 6092.79,4920.77 6111.64,4901.93 6111.64,4742.97 6176.64,4677.97 v1(6207.64,4677.97) ; C26.2@6511.68,4503.51 6554.46,4460.73 U15.3@6554.46,4448.37
  other v1: 6548.64,4460.97
$1N24358: CN5.4 R41.1 U18.7 | length 869.5
  Top Layer w10: v1(5983.64,5472.97) 6017.64,5438.97 v1(6017.64,5059.97)
  Bottom Layer w10: CN5.4@5968.24,5541.95 5983.64,5526.55 v1(5983.64,5472.97) ; U18.7@5979.09,4826 5912.2,4826 R41.1@5904.24,4818.04 5904.24,4938.57 5937.64,4971.97 5937.64,4979.97 v1(6017.64,5059.97)
$1N24662: U9.6 U18.3 | length 701
  Bottom Layer w10: U18.3@6197.39,4776 6177.6,4776 6143.64,4809.97 6143.64,4897.97 6215.64,4969.97 6215.64,5210.97 6355.27,5350.6 U9.6@6355.27,5355.47
$1N24669: R39.2 R40.1 U18.2 | length 141.4
  Bottom Layer w10: U18.2@6197.39,4826 6206.35,4834.96 R40.1@6272.24,4834.96 6271.52,4834.24 R39.2@6271.52,4772.45
$1N24724: R41.2 R42.2 U18.6 | length 143.6
  Bottom Layer w10: R42.2@5903.6,4718.76 5904.24,4719.4 R41.2@5904.24,4783.96 5971.13,4783.96 U18.6@5979.09,4776
$1N24768: U9.7 U18.5 | length 1217.6
  Top Layer w10: v1(6194.64,4564.97) 6194.64,4617.97 v1(6212.64,4635.97)
  Bottom Layer w10: U18.5@5979.09,4726 6140.13,4564.97 v1(6194.64,4564.97) ; v1(6212.64,4635.97) 6229.64,4635.97 6308.64,4714.97 6308.64,4923.97 6244.64,4987.97 6244.64,5202.97 6257.64,5215.97 6269.98,5215.97 6374.95,5320.94 U9.7@6374.95,5355.47
$1N24779: CN4.4 R40.2 U18.1 | length 1001.9
  Top Layer w10: v1(6218.64,4875.97) 6218.64,4986.97 6138.64,5066.97 6128.64,5066.97 6103.64,5091.97 6103.64,5268.97 6308.64,5473.97 v1(6368.64,5473.97)
  Bottom Layer w10: U18.1@6197.39,4876 v1(6218.64,4875.97) ; v1(6218.64,4875.97) 6265.28,4876 R40.2@6272.24,4869.04 ; v1(6368.64,5473.97) 6400.26,5473.97 CN4.4@6468.24,5541.95
A_SIG: K10.2 R29.2 U7.2 | length 2550.5
  Inner1 w10: v1(4599.64,3924.97) 4599.64,3891.97 4734.64,3756.97 4760.64,3756.97 4915.64,3911.97 5088.64,3911.97 5222.64,4045.97 5222.64,4063.97 5244.64,4085.97 5801.64,4085.97 v1(6012.64,3874.97)
  Bottom Layer w10: U7.2@4305.64,3845.67 4305.64,3778.97 4309.61,3775 4378.25,3775 4425.46,3727.79 4569.72,3727.79 4592.93,3751 4663.84,3751 4673.84,3761 4736.85,3761 4736.85,3876.76 4730.64,3882.97 4730.64,3889.97 4718.64,3901.97 4706.64,3901.97 4683.64,3924.97 v1(4599.64,3924.97) ; v1(6012.64,3874.97) 6012.64,3871.97 v1@6013.64,3870.97
  other v1: 6000.64,3474.46
ADC-CS-0: U6.10 U14.29 | length 2280
  Inner1 w10: v1(4196.64,3558.97) 4710.64,3558.97 v1(5020.64,3868.97)
  Bottom Layer w10: U6.10@4082.64,3636.27 4082.64,3592.47 4116.14,3558.97 v1(4196.64,3558.97) ; U14.29@4975.41,4827.34 5002.06,4827.34 5003.44,4825.97 5030.64,4825.97 5085.64,4770.97 5085.64,4547.97 5035.64,4497.97 5035.64,4429.97 5045.64,4419.97 5045.64,4150.8 5061.25,4135.19 5103.42,4135.19 5118.64,4119.97 5118.64,3966.97 v1(5020.64,3868.97)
